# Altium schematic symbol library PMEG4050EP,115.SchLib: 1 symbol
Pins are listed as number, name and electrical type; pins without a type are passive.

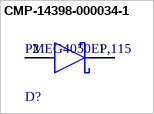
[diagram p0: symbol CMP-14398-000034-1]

## CMP-14398-000034-1
designator D?, comment PMEG4050EP,115
DIODE SCHOTTKY 40V 5A CFP5
footprint FP-SOD128-MFG
pins: 1 K, 2 A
